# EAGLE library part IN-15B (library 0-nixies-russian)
IN-15B: medium symbol topview nixie tube
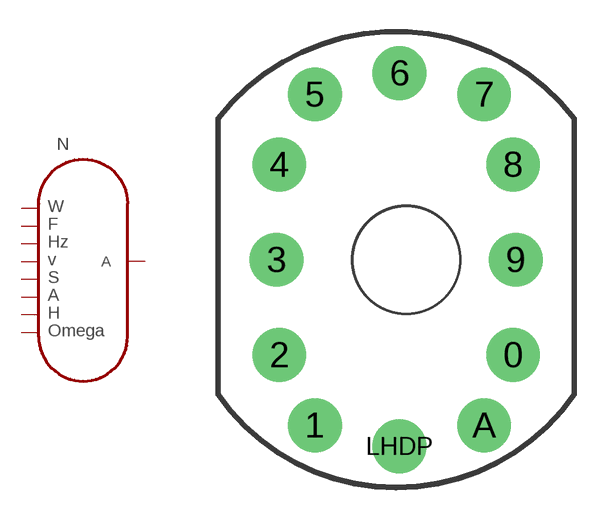
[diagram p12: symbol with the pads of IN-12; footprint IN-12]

Designator prefix N

## IN-15B  [IN-12]
0  P$1
1  P$6
2  P$8
4  P$5
5  P$4
6  P$7
7  P$3
9  P$2
A  A

## Footprint IN-12 (pad centres in mm)
May be used with socket: SK-136
drill 1.1 pad 2.54 round: 0 5.048,-4.5; 1 -4.317,-7.817; 2 -6,-4.5; 3 -6.127,0; 4 -6,4.5; 5 -4.317,7.817; 6 -0.318,8.818; 7 3.683,7.817; 8 5.048,4.5; 9 5.175,0; A 3.683,-7.817; LHDP -0.318,-8.818
hole 5 at 0,0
